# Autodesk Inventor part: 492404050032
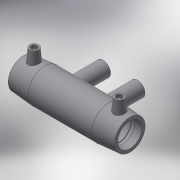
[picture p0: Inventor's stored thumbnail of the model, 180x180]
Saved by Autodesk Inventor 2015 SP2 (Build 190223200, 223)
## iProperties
Created: 2017-06
Part Number: 492404050032
Material: Generic
Description: PLASSON REDUCING TEE WITH TWO OUTLETS 50X32X32X50
Document SubType Name: Modeling
Designer: KIM
Mass: 57.3761 g
Surface Area: 241.06 cm^2
Volume: 57.3761 cm^3
Density: 1 g/cm^3
Appearance: Default
Author: KIM
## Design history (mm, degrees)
derived "492404.ipt"
feature "Solid1::492404.ipt"
tag "TaggingFeature1"
body "Solid1"
other parameters: "d0" = 195, "d2" = 68, "d3" = 49, "d4" = 39, "d5" = 61.2, "d6" = 47.5, "d8" = 168 deg, "d10" = 19.6, "d11" = 6.53333, "d23" = 68, "d29" = 51, "d30" = 15, "d31" = 78, "d34" = 5 deg, "d41" = 4, "d42" = 14, "d43" = 0, "d48" = -83, "d49" = 32, "d51" = 0, "d62" = 83, "d74" = -83, "d84" = 32, "d85" = 65, "d86" = 32.5, "d87" = 25.6, "d88" = 25.6, "d90" = 0, "d91" = 3, "d92" = 0, "L_" = 195, "L_1" = 49, "D_" = 68, "A_" = 51, "d_2" = 12, "H_" = 83, "L_2" = 65, "d_1" = 32
